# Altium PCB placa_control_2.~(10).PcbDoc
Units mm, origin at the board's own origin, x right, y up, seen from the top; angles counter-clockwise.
Board outline 71.3 x 86.83 mm, 2 copper layers (Top Layer, Bottom Layer); 40 components, 36 nets, 154 pads, 91 vias.
Unrouted connection lines stored in the file: 1.
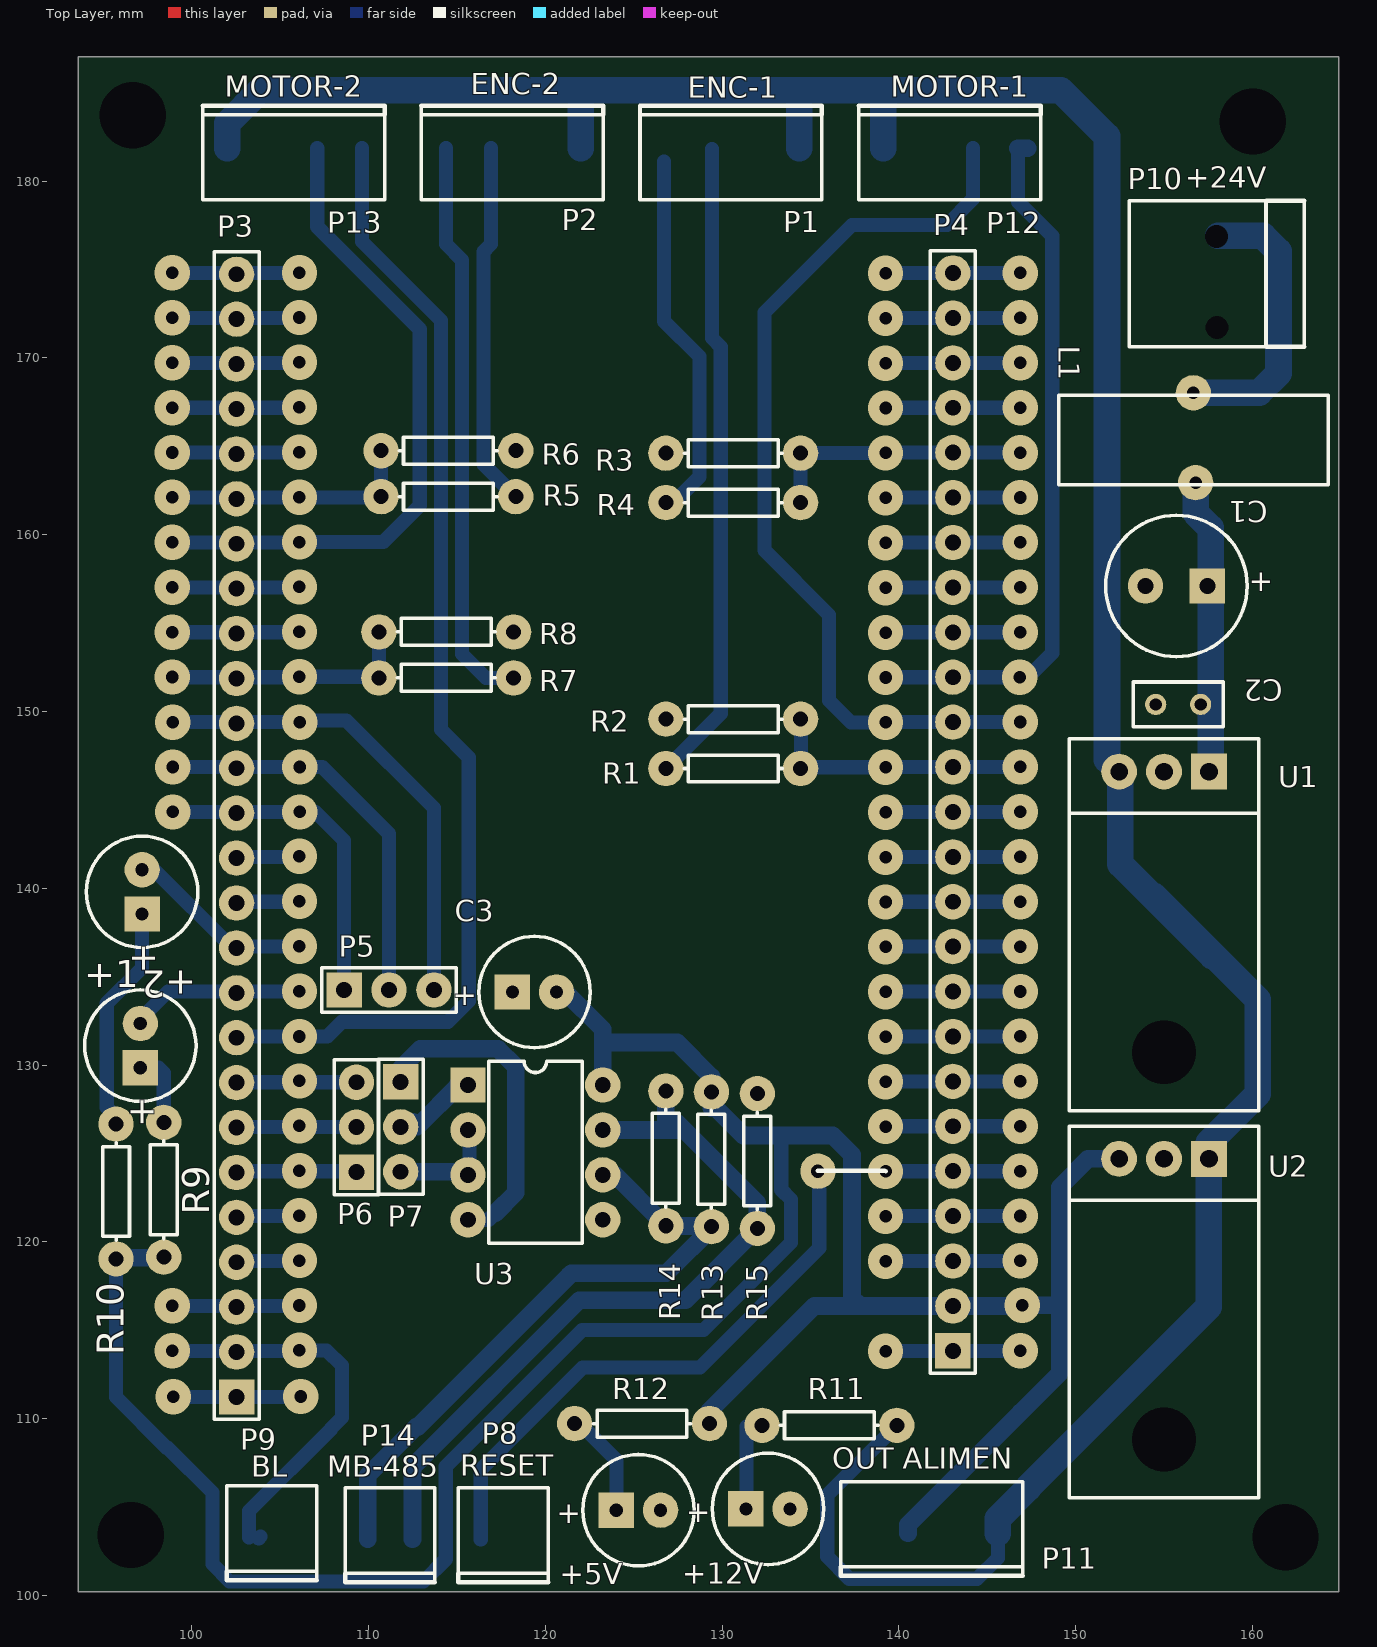
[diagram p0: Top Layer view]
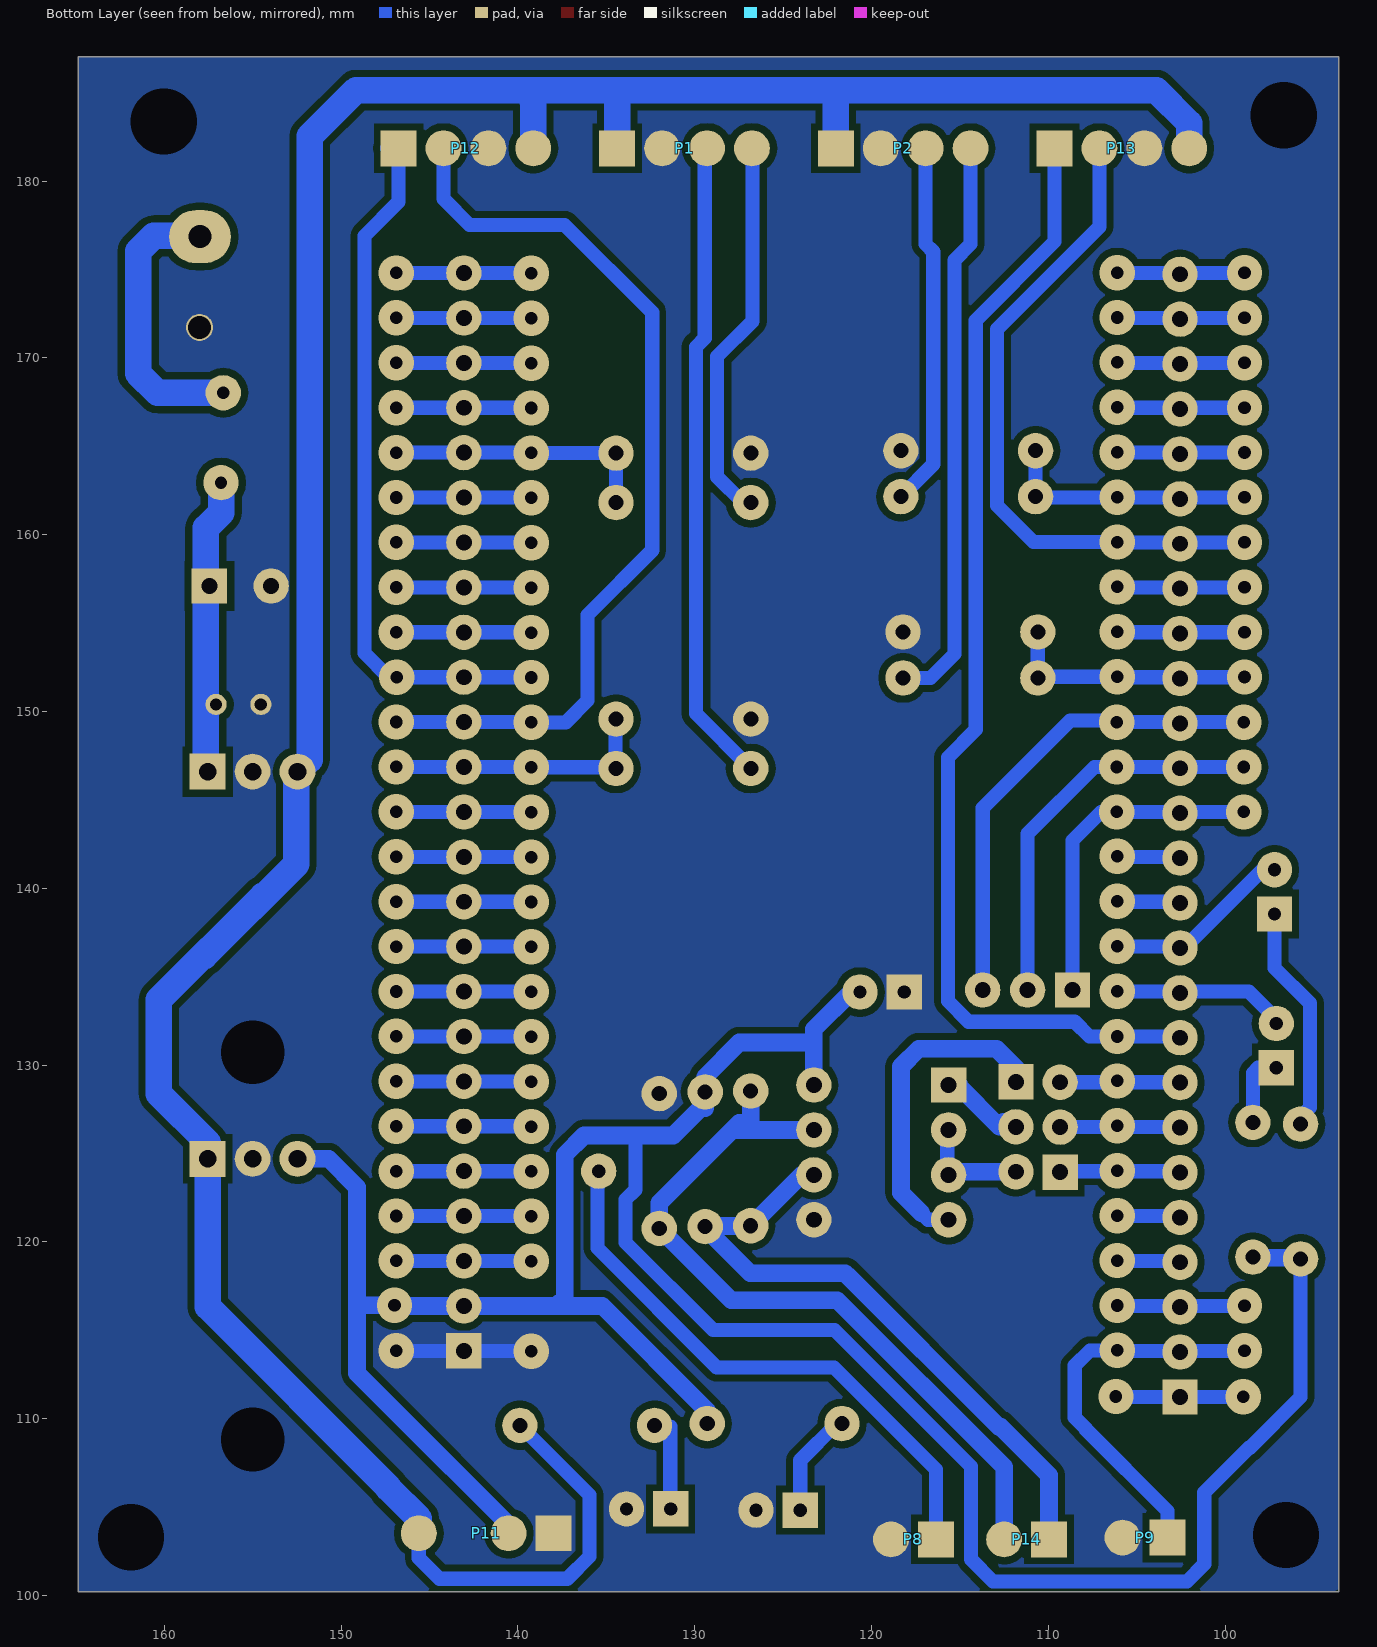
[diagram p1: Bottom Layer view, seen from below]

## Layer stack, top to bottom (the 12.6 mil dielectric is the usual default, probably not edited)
Top Layer: signal copper 0.0356
Dielectric: dielectric 0.32, FR-4, Dk 4.8
Bottom Layer: signal copper 0.0356

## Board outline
93.575,187.025 164.875,187.025 164.875,100.2 93.575,100.2

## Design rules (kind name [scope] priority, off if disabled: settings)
Clearance [All] p1: gap=0.4
ComponentClearance [All] p1: gap=0.254 collisioncheckmode=2 verticalgap=0.254
PlaneConnect [All] p1: planeconnectstyle=Direct reliefexpansion=0.508 reliefentries=4 reliefconductorwidth=0.6 reliefairgap=0.254
PolygonConnect [All] p1: connectstyle=Direct reliefconductorwidth=0.6 reliefentries=4 polygonreliefangle="90 Angle"
RoomDefinition REGULADOR [InComponentClass('REGULADOR')] p1: confinementstyle=ConfineIn formatcopy=TRUE lockcomponents=FALSE outline 120.125,100.175 164.9,100.175 164.9,183.6 120.125,183.6
RoomDefinition INTERFAZ [InComponentClass('INTERFAZ')] p2: confinementstyle=ConfineIn formatcopy=TRUE lockcomponents=FALSE outline 107.1,115.025 140,115.025 140,140.425 107.1,140.425
RoomDefinition ENCODER [InComponentClass('ENCODER')] p3: confinementstyle=ConfineIn formatcopy=TRUE lockcomponents=FALSE outline 149.325,144.075 149.325,186.3 99.15,186.3 99.15,144.075
RoomDefinition BOARD-ARM [InComponentClass('BOARD-ARM')] p4: confinementstyle=ConfineIn formatcopy=TRUE lockcomponents=FALSE outline 148.263,99.75 93.575,99.75 93.575,180.275 148.263,180.275
RoomDefinition placa_control_esquema [InComponentClass('placa_control_esquema')] p5: confinementstyle=ConfineIn formatcopy=TRUE lockcomponents=FALSE outline 93.575,100.175 164.875,100.175 164.875,187.025 93.575,187.025
RoutingVias [All] p1: holewidth=0.711 width=2 viastyle="Through Hole" minholewidth=0.711 minwidth=1.27 maxholewidth=0.711 maxwidth=2
SolderMaskExpansion [All] p1: expansion=0.102
TestPointUsage [All] p1: valid=0 allowmultiple=FALSE
Testpoint [All] p1: side=15 testpointundercomponent=TRUE minsize=1.016 maxsize=2.54 preferedsize=1.524 minholesize=0 maxholesize=1.016 preferedholesize=0.813 testpointgrid=0.025 style=1023 order=0123456789
Width [All] p1: maxlimit=1.5 minlimit=0.8 preferedwidth=0.8
17 further rules are at their usual default settings.

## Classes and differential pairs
component class placa_control_esquema: P11 P12 P13
component class REGULADOR: +5V +12V C1 C2 L1 P10 R11 R12 U1 U2
component class BOARD-ARM: +1 +2 P3 P4 P5 P6 P7 P8 P9 R9 R10
component class ENCODER: P1 P2 R1 R2 R3 R4 R5 R6 R7 R8
component class INTERFAZ: C3 P14 R13 R14 R15 U3

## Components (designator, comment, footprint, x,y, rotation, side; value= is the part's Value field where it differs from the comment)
+1 "LED2" CAPPR2.5-6.3X5 97.1,131.1 r90 top
+2 "LED2" CAPPR2.5-6.3X5 97.2,139.8 r90 top
+5V "LED2" CAPPR2.5-6.3X5 125.275,104.825 r0 top (schematic designator +4)
+12V "LED2" CAPPR2.5-6.3X5 132.6,104.9 r0 top (schematic designator +3)
C1 "Cap Pol3" CAPPR3.5-8X15 155.7,157.1 r180 top
C2 "Cap" RAD-0.1 155.8,150.4 r0 top
C3 "Cap" CAPPR2.5-6.3X5 119.394,134.133 r0 top
L1 "Inductor Iron" bobina_Choque 159.2,167.9 r180 top
P1 "ENC-1" HDR1X5#1 126.758,189.475 r180 top
P2 "ENC-2" HDR1X5#1 114.392,189.475 r180 top
P3 "header26" HDR1x26 107.625,144.25 r90 top
P4 "Header 25" HDR1X25 143.055,113.84 r90 top
P5 "Header 3" HDR1X3 108.625,134.25 r0 top
P6 "Header 3" HDR1X3 109.325,123.95 r90 top
P7 "Header 3" HDR1X3 111.825,129.05 r270 top
P8 "RESET" wf2s 123.975,103.175 r0 top
P9 "BL" wf2s 110.875,103.275 r0 top
P10 "+24V" PWHEADER1X2 157.975,174.95 r90 top
P11 "OUT ALIMEN" HDR1X5#2 145.6,95.9 r0 top
P12 "MOTOR-1" HDR1X5#1 139.125,189.475 r180 top
P13 "MOTOR-2" HDR1X5#1 102.025,189.475 r180 top
P14 "MB-485" wf2s 117.575,103.175 r0 top
R1 "metal film 2%" AXIAL-0.3 130.634,146.777 r180 top
R2 "metal film 2%" AXIAL-0.3 130.634,149.569 r0 top
R3 "metal film 2%" AXIAL-0.3 130.634,161.818 r180 top
R4 "metal film 2%" AXIAL-0.3 130.634,164.61 r0 top
R5 "metal film 2%" AXIAL-0.3 114.525,162.15 r0 top
R6 "metal film 2%" AXIAL-0.3 114.525,164.75 r180 top
R7 "metal film 2%" AXIAL-0.3 114.4,151.9 r0 top
R8 "metal film 2%" AXIAL-0.3 114.4,154.5 r180 top
R9 "Carbon 1/8w 5%" AXIAL-0.3 98.425,122.95 r90 top
R10 "Carbon 1/8w 5%" AXIAL-0.3 95.725,122.85 r90 top
R11 "Carbon 1/8w 5%" AXIAL-0.3 136.075,109.625 r0 top
R12 "Carbon 1/8w 5%" AXIAL-0.3 125.475,109.725 r0 top
R13 "Carbon 1/8w 5%" AXIAL-0.3 129.4,124.675 r90 top
R14 "Carbon 1/8w 5%" AXIAL-0.3 126.826,124.725 r270 top
R15 "Carbon 1/8w 5%" AXIAL-0.3 132,124.575 r270 top
U1 "LM78L12ACZ" T03B 155,146.6 r180 top
U2 "LM78L05ACZ" T03B 155,124.7 r180 top
U3 "SN75176BP" 626-05 119.444,125.065 r270 top

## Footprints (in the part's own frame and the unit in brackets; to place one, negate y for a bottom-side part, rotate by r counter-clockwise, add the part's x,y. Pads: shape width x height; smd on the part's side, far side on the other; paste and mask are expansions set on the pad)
626-05 [mm] "DIP; 8 Leads; Row Spacing 7.62 mm; Pitch 2.54 mm"
  rect 2x2 hole 0.9: 1(-3.81,-3.81)
  round 2 hole 0.9: 2(-1.27,-3.81) 3(1.27,-3.81) 4(3.81,-3.81) 5(3.81,3.81) 6(1.27,3.81) 7(-1.27,3.81) 8(-3.81,3.81)
  silkscreen extent -5.15,-2.65 5.15,2.65
AXIAL-0.3 [mm] "Resistor; 2 Leads"
  round 2 hole 0.85: 1(-3.81,0) 2(3.81,0)
  silkscreen extent -2.77,-0.76 2.77,0.76
bobina_Choque [mm]
  round 2 hole 0.7: 1(2.54,-0.127) 2(2.413,4.953)
  silkscreen extent -5.08,0 10.16,5.08
CAPPR2.5-6.3X5 [mm] "Capacitor, Electrolytic, Radial; Body 6.3 x 5 mm (Dia.xH typ); Pin Spacing 2.5 mm (typ)"
  rect 2x2 hole 0.75: 1(-1.25,0)
  round 2 hole 0.75: 2(1.25,0)
  silkscreen extent -3.15,-3.15 3.15,3.15
CAPPR3.5-8X15 [mm] "Capacitor, Electrolytic, Radial; Body 8 x 15 mm (Dia.xH typ); Pin Spacing 3.5 mm (typ)"
  rect 2x2 hole 0.9: 1(-1.75,0)
  round 2 hole 0.9: 2(1.75,0)
  silkscreen extent -4,-4 4,4
HDR1X3 [mm] "Connector; Header; 3 Position"
  rect 2x2 hole 0.9: 1(0,0)
  round 2 hole 0.9: 2(2.54,0) 3(5.08,0)
  silkscreen extent -1.27,-1.27 6.35,1.27
HDR1X5#1 [mil]
  rect 80x80 smd far side: 1(-300,300)
  round 80 smd far side: 2(-200,300) 3(-100,300) 4(0,300)
  silkscreen extent -350,205 55,415
HDR1X5#2 [mil]
  rect 80x80 smd far side: 1(-300,300)
  round 80 smd far side: 2(-200,300) 4(0,300)
  silkscreen extent -350,205 55,415
HDR1X25 [mm] "Connector; Header; 25 Position"
  rect 2x2 hole 0.9: 1(0,0)
  round 2 hole 0.9: 2(2.54,0) 3(5.08,0) 4(7.62,0) 5(10.16,0) 6(12.7,0) 7(15.24,0) 8(17.78,0) 9(20.32,0) 10(22.86,0) 11(25.4,0) 12(27.94,0) 13(30.48,0) 14(33.02,0) 15(35.56,0) 16(38.1,0) 17(40.64,0) 18(43.18,0) 19(45.72,0) 20(48.26,0) 21(50.8,0) 22(53.34,0) 23(55.88,0) 24(58.42,0) 25(60.96,0)
  silkscreen extent -1.27,-1.27 62.23,1.27
HDR1x26 [mm]
  rect 2x2 hole 0.9: 1(-33.02,5.08)
  round 2 hole 0.9: 2(-30.48,5.08) 3(-27.94,5.08) 4(-25.4,5.08) 5(-22.86,5.08) 6(-20.32,5.08) 7(-17.78,5.08) 8(-15.24,5.08) 9(-12.7,5.08) 10(-10.16,5.08) 11(-7.62,5.08) 12(-5.08,5.08) 13(-2.54,5.08) 14(0,5.08) 15(2.54,5.08) 16(5.08,5.08) 17(7.62,5.08) 18(10.16,5.08) 19(12.7,5.08) 20(15.24,5.08) 21(17.78,5.08) 22(20.32,5.08) 23(22.86,5.08) 24(25.4,5.08) 25(27.94,5.08) 26(30.48,5.08)
  silkscreen extent -34.29,3.81 31.75,6.35
PWHEADER1X2 [mm]
  round 0 / inner round 0 / far side oval 3x3.5 hole 1.3: 2(1.905,0)
  silkscreen extent -4.32,-4.95 3.94,4.95
RAD-0.1 [mm] "Indicating Instrument; 2 Leads"
  round 1.2 hole 0.7: 1(-1.27,0) 2(1.27,0)
  silkscreen extent -2.54,-1.27 2.54,1.27
T03B [mil] "TO, Thru-Hole, Vertical, Heatsink Mounted; 3 In-Line Leads; Pitch 2.54 mm"
  rect 80x80 hole 39.37: 1(-100,0)
  round 80 hole 39.37: 2(0,0) 3(100,0)
  round 80 hole 141.73: 4(0,625)
  silkscreen extent -211,-73 211,755
wf2s [mil]
  rect 80x80 smd far side: 1(-300,0)
  round 80 smd far side: 2(-200,0)
  silkscreen extent -350,-95 -150,115

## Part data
+1 +2 +5V +12V: "Typical RED, GREEN, YELLOW, AMBER GaAs LED"
C1: "Polarized Capacitor 35V"
C2 C3: "Capacitor"
L1: "Magnetic-Core Inductor"
P1 P2 P11 P12 P13: library part "Header 4", "Header, 4-Pin"
P3: library part Component_1
P4: "Header, 25-Pin"
P5 P6 P7: "Header, 3-Pin"
P8 P9 P10 P14: library part "Header 2", "Header, 2-Pin"
R1 R2 R3 R4 R5 R6 R7 R8 R9 R10 R11 R12 R13 R14 R15: library part "Res Semi", "Semiconductor Resistor"
U1 U2: "3-Terminal Positive Regulator"
U3: "Differential Bus Transceiver"

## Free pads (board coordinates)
  round 1.524 hole 3.75: 0(96.55,103.425) 0(96.675,183.725) 0(160.025,183.375) 0(161.875,103.3)
  round 2 hole 0.762: 0(135.425,124)
  round 0 / inner round 0 / far side round 1.524 hole 1.3: 0(158,171.725)

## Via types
v1: diameter 2, hole 0.711, Top Layer to Bottom Layer, 91 vias

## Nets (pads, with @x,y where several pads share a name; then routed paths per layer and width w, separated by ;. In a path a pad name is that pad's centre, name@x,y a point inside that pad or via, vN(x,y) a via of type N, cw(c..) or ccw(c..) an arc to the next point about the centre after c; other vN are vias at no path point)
+5V: C3.2 P4.2 P11.2 R9.1 R10.1 R12.2 R13.2 U2.3 U3.8 | length 152.5
  Bottom Layer w0.8: R10.1 95.725,111.225 98.589,108.361 98.639,108.361 101.175,105.825 101.175,101.775 102.15,100.8 113.125,100.8 114.375,102.05 ; 114.375,102.075 114.375,107.307 122.093,115.025 128.95,115.025 133.9,119.975 133.9,122.4 133.35,122.95 133.35,126.018
  Bottom Layer w1: R10.1 95.785,119.1 R9.1@98.525,119.1 ; C3.2@121.142,134.133 123.254,132.021 U3.8 ; 123.254,131.275 127.475,131.275 R13.2@129.4,129.35 ; R12.2@129.285,110.435 135.23,116.38 P4.2 143.06,116.375 v1@146.325,116.375 ; R13.2@129.4,127.575 129.4,127.825 131.207,126.018 136.257,126.018 137.35,124.925 137.35,116.38 ; 137.48,116.38 137.65,116.55 ; P11.2 140.52,103.995 146.887,110.362 149.095,112.57 149.095,123.095 150.7,124.7 U2.3 ; v1(146.975,116.425) 148.775,116.425
+12V: P1.1 P2.1 P11.4 P12.4 P13.4 R11.2 U1.3 U2.1 | length 176
  Bottom Layer w0.8: R11.2 135.95,105.69 135.95,102.2 137.2,100.95 144.425,100.95 145.6,102.125 P11.4
  Bottom Layer w1.5: P13.4 102.025,183.275 103.9,185.15 149.15,185.15 151.775,182.525 151.775,147.285 152.525,146.535 152.525,141.375 157.74,136.16 ; P2.1 122.012,184.637 122.025,184.65 ; P1.1 134.378,184.603 134.425,184.65 ; P12.4 139.125,184.575 139.2,184.65 ; P11.4 145.6,104.35 147.317,106.067 147.317,106.117 157.54,116.34 157.54,125.615 160.3,128.375 160.3,133.7 154.425,139.575
D/~E: P7.3 U3.2 U3.3 | length 6.7
  Bottom Layer w0.8: U3.3 115.71,123.87 115.71,126.365 U3.2@115.75,126.325
  Bottom Layer w1: P7.3 115.459,123.97 U3.3 ; U3.3@115.615,124.27 U3.3@115.71,124.175
D/~E_0: P3.14 P5.1 | length 18.8
  Bottom Layer w0.8: v1(98.94,144.32) 107.005,144.32 108.625,142.7 P5.1
  other v1: 106.125,144.32
D/~E_1: P3.6 P6.1 | length 6.9
  Bottom Layer w0.8: P3.6@102.45,124 109.275,124 P6.1
  other v1: 106.1,124.025
DRIVER: P7.1 U3.4 | length 18.6
  Bottom Layer w0.8: U3.4 116.805,121.255 117.187,121.637
  Bottom Layer w1: P7.1 111.825,129.825 112.925,130.925 117.325,130.925 118.325,129.925 118.325,122.775 117.187,121.637
ENC1_FASEZ: P4.21 R3.1 R4.2 | length 15
  Bottom Layer w0.8: R3.1@134.294,162.4 R3.1@134.319,162.425 ; R4.2@134.294,164.575 134.344,164.625 v1(139.25,164.625) ; R4.2@134.319,164.575 R4.2@134.319,164.6 ; R3.1 R4.2 ; v1@139.555,164.64 v1@146.74,164.64
  other v1: 146.875,164.645
ENC2_FASEZ: P3.17 R7.1 R8.2 | length 14.4
  Bottom Layer w0.8: v1@98.94,151.94 v1@106.125,151.94 ; v1(106.1,151.965) 110.485,151.965 R7.1@110.65,151.8 ; R7.1 R8.2
  other v1: 98.9,151.95
GND: +5V.2 +12V.2 C1.2 C2.1 C3.1 P1.2 P2.2 P4.1 P8.2 P9.2 P11.1 P12.3 P13.3 pad.0@96.55,103.425 pad.0@96.675,183.725 pad.0@158,171.725 pad.0@160.025,183.375 pad.0@161.875,103.3 R2.1 R4.1 R6.1 R8.1 R15.1 U1.2 U1.4 U2.2 U2.4 U3.5 | length 7.2
  Bottom Layer w0.8: v1@139.555,113.84 v1@146.74,113.84
  other v1: 139.25,113.825 146.875,113.845
IN_B_L: P3.2 P9.1 | length 22
  Bottom Layer w0.8: v1@98.94,113.84 v1@106.125,113.84 ; P9.1 103.255,104.78 107.875,109.4 107.875,109.45 108.5,110.075 108.5,113 107.635,113.865 v1(106.1,113.865) ; P9.1@103.795,103.225 P9.1@103.9,103.33
  other v1: 98.9,113.85
IN_SD_1: P4.15 P12.2 | length 51.7
  Bottom Layer w0.8: v1(139.25,149.385) 137.29,149.385 136.06,150.615 136.06,155.465 132.4,159.125 132.4,172.575 137.35,177.525 142.725,177.525 144.205,179.005 P12.2 ; v1@139.555,149.4 v1@146.74,149.4
  other v1: 146.875,149.405
IN_SD_2: P3.20 P13.2 | length 37.4
  Bottom Layer w0.8: v1@98.94,159.56 v1@106.125,159.56 ; v1(106.1,159.585) 110.835,159.585 112.9,161.65 112.9,171.625 107.105,177.42 P13.2
  other v1: 98.9,159.57
LED_1: +1.2 P3.10 | length 9.9
  Bottom Layer w0.8: +1.2 97.1,132.6 98.66,134.16 v1@106.1,134.16
  other v1: 106.1,134.185
LED_2: +2.2 P3.11 | length 10.8
  Bottom Layer w0.8: +2.2@96.9,141.05 97.875,141.05 P3.11@102.225,136.7 ; P3.11@102.5,136.7 v1@106.125,136.7
  other v1: 106.1,136.725
Net+1_1: +1.1 R9.2 | length 4.2
  Bottom Layer w0.8: +1.1 98.125,129.85 98.425,129.55 R9.2
Net+2_1: +2.1 R10.2 | length 12.9
  Bottom Layer w0.8: R10.2@95.625,126.625 95.625,127.175 95.2,127.6 95.2,133.5 97.2,135.5 +2.1
Net+3_1: +12V.1 R11.1 | length 5.1
  Bottom Layer w0.8: +12V.1@131.375,105.1 R11.1@131.375,109.565 ; R11.1 R11.1@132.7,109.19
Net+4_1: +5V.1 R12.1 | length 6
  Bottom Layer w0.8: R12.1 121.95,109.725 124.025,107.65 +5V.1
NetC1_1: C1.1 C2.2 L1.2 U1.1 | length 15.9
  Bottom Layer w1.5: L1.2@156.787,162.147 156.787,161.238 157.64,160.385 U1.1@157.64,146.6
NetL1_1: L1.1 P10.2 | length 15.9
  Bottom Layer w1.5: L1.1 160.377,168.027 161.475,169.125 161.475,176.025 160.6,176.9 P10.2@158.075,176.9
NetP1_3: P1.3 R1.2 | length 36.5
  Bottom Layer w0.8: R1.2 129.925,149.878 129.925,170.625 129.425,171.125 P1.3@129.425,181.825
NetP1_4: P1.4 R3.2 | length 21.2
  Bottom Layer w0.8: P1.4@126.725,181.1 126.725,172.075 128.725,170.075 128.725,163.275 127.268,161.818 R3.2
NetP2_3: P2.3 R5.2 | length 20.6
  Bottom Layer w0.8: P2.3 116.932,176.434 116.5,176.002 116.5,163.985 R5.2
NetP2_4: P2.4 R7.2 | length 32.5
  Bottom Layer w0.8: P2.4 114.392,176.433 115.3,175.525 115.3,153.25 116.65,151.9 R7.2
NetP3_21: P3.21 R5.1 R6.2 | length 14.6
  Bottom Layer w0.8: v1@98.8,162.1 110.705,162.1 110.715,162.09 R6.2
  other v1: 98.9,162.11 106.1,162.125
NetP4_14: P4.14 R1.1 R2.2 | length 15
  Bottom Layer w0.8: R1.1@134.375,146.875 134.405,146.845 v1(139.25,146.845) v1@139.182,146.777 ; R1.1@134.475,146.9 R2.2@134.475,149.75 ; v1@139.555,146.86 v1@146.74,146.86
  other v1: 146.875,146.865
NetP14_1: P14.1 R13.1 R14.2 U3.6 | length 36.9
  Bottom Layer w1: P14.1 109.955,106.805 112.725,109.575 ; 112.775,109.525 121.35,118.1 ; 120.629,117.379 121.475,118.225 126.85,118.225 R13.1@129.6,120.975 ; U3.6@123.946,123.795 R14.2@126.566,121.175 ; R14.2 R14.2@126.826,121.301 ; R14.2@126.95,120.95 127.004,120.896 R13.1@129.521,120.896 ; R13.1@129.35,120.915 R13.1
NetP14_2: P14.2 R14.1 R15.2 U3.7 | length 44.1
  Bottom Layer w1: P14.2 112.495,107.265 121.93,116.7 127.935,116.7 R15.2 ; U3.7 127.865,126.335 ; R14.1@126.866,128.575 R14.1 126.826,126.724 127.476,126.724 132,122.2 132,120.775 R15.2@131.995,120.77
PWM_1: P4.16 P12.1 | length 39.6
  Bottom Layer w0.8: v1@139.555,151.94 147.315,151.94 148.675,153.3 148.675,176.9 146.745,178.83 P12.1
  Bottom Layer w1: P12.1 P12.1@147.295,181.855
  other v1: 139.25,151.925 146.85,151.94
PWM_2: P3.9 P13.1 | length 64.8
  Bottom Layer w0.8: P3.9@102.475,131.62 107.67,131.62 108.5,132.45 114.5,132.45 115.675,133.625 115.675,147.4 114.1,148.975 114.1,172.125 109.645,176.58 P13.1
  other v1: 106.1,131.62
RECIEVER: P7.2 U3.1 | length 5.1
  Bottom Layer w1: P7.2 112.76,126.51 U3.1@115.15,128.9 ; P7.2@112.425,126.8 P7.2@112.525,126.8 ; U3.1@115.05,128.9 U3.1@115.775,128.9
RESET: P4.5 P8.1 pad.0@135.425,124 | length 39.8
  Bottom Layer w0.8: P8.1 116.355,107.13 122.125,112.9 128.75,112.9 135.5,119.65 135.5,122.85 pad.0@135.425,124 ; v1@139.555,124 v1@146.74,124
  other v1: 139.25,123.985 146.875,124.005
RX_0: P3.15 P5.2 | length 22.6
  Bottom Layer w0.8: v1(98.94,146.86) 107.39,146.86 111.165,143.085 P5.2
  other v1: 106.125,146.86
RX_1: P3.7 P6.2 | length 6.2
  Bottom Layer w0.8: P3.7@102.2,126.49 P6.2@108.325,126.49 ; P6.2@109.275,126.54 P6.2
  other v1: 106.1,126.565
TX_0: P3.16 P5.3 | length 27.1
  Bottom Layer w0.8: v1(98.94,149.4) v1(106.125,149.4) ; v1@106.15,149.5 108.75,149.5 113.705,144.545 P5.3
TX_1: P3.8 P6.3 | length 6.8
  Bottom Layer w0.8: P3.8@102.475,129.03 P6.3
  other v1: 106.1,129.105
pads on no net: P3.1 P3.3 P3.4 P3.5 P3.12 P3.13 P3.18 P3.19 P3.22 P3.23 P3.24 P3.25 P3.26 P4.3 P4.4 P4.6 P4.7 P4.8 P4.9 P4.10 P4.11 P4.12 P4.13 P4.17 P4.18 P4.19 P4.20 P4.22 P4.23 P4.24 P4.25
copper on no net: | length 209.2
  Bottom Layer w0.8: v1@98.9,164.64 v1@106.215,164.64 ; v1@98.94,116.38 v1@106.125,116.38 ; v1@98.94,154.48 v1@106.125,154.48 ; v1@98.94,157.02 v1@106.125,157.02 ; v1@98.94,167.18 v1@106.125,167.18 ; v1@98.94,169.72 v1@106.125,169.72 ; v1@98.94,172.26 v1@106.125,172.26 ; v1@98.94,174.8 v1@106.125,174.8 ; v1@99.01,111.23 v1@106.195,111.23 ; 102.325,121.46 v1@106.125,121.46 ; 102.35,118.92 v1@106.125,118.92 ; 102.375,139.24 v1@106.125,139.24 ; 102.425,141.78 v1@106.125,141.78 ; v1@139.555,118.92 v1@146.74,118.92 ; v1@139.555,121.46 v1@146.74,121.46 ; v1@139.555,126.54 v1@146.74,126.54 ; v1@139.555,129.08 v1@146.74,129.08 ; v1@139.555,131.62 v1@146.74,131.62 ; v1@139.555,134.16 v1@146.74,134.16 ; v1@139.555,136.7 v1@146.74,136.7 ; v1@139.555,139.24 v1@146.74,139.24 ; v1@139.555,141.78 v1@146.74,141.78 ; v1@139.555,144.32 v1@146.74,144.32 ; v1@139.555,154.48 v1@146.74,154.48 ; v1@139.555,157.02 v1@146.74,157.02 ; v1@139.555,159.56 v1@146.74,159.56 ; v1@139.555,162.1 v1@146.74,162.1 ; v1@139.555,167.18 v1@146.74,167.18 ; v1@139.555,169.72 v1@146.74,169.72 ; v1@139.555,172.26 v1@146.74,172.26 ; v1@139.555,174.8 v1@146.74,174.8
  other v1: 98.97,111.24 106.17,111.255 98.9,116.39 106.1,116.405 139.25,118.905 146.875,118.925 106.1,118.945 139.25,121.445 146.875,121.465 106.1,121.485 139.25,126.525 146.875,126.545 139.25,129.065 146.875,129.085 139.25,131.605 146.875,131.625 139.25,134.145 146.875,134.165 139.25,136.685 146.875,136.705 139.25,139.225 146.875,139.245 106.1,139.265 139.25,141.765 146.875,141.785 106.1,141.805 139.25,144.305 146.875,144.325 139.25,154.465 98.9,154.49 146.875,154.485 106.1,154.505 139.25,157.005 98.9,157.03 146.875,157.025 106.1,157.045 139.25,159.545 146.875,159.565 139.25,162.085 146.875,162.105 98.9,164.65 106.1,164.665 139.25,167.165 98.9,167.19 146.875,167.185 106.1,167.205 139.25,169.705 98.9,169.73 146.875,169.725 106.1,169.745 139.25,172.245 98.9,172.27 146.875,172.265 106.1,172.285 139.25,174.785 98.9,174.81 146.875,174.805 106.1,174.825

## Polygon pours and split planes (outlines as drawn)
GND on Bottom Layer "plano_señal_fuerte" (solid, remove dead copper, pour order 1000): 93.6,187.039 93.662,187.075 164.9,187.075 164.869,187.057 164.869,100.293 164.9,100.275 93.756,100.275 93.662,100.33 93.6,100.366

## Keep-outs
Drill Guide:
  rectangle: 100.3,106.525 145.7,176.725

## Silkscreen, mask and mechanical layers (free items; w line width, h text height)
Top Overlay:
  lines w0.254: 135.425,124.025 139.21,124.025 139.25,123.985
Drill Drawing:
  lines w0.254: 93.425,72.425 93.475,72.475

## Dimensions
165.875,38.05 to 92.95,39.475 on Drill Drawing
91.375,190.675 to 89.933,43.649 on Drill Drawing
